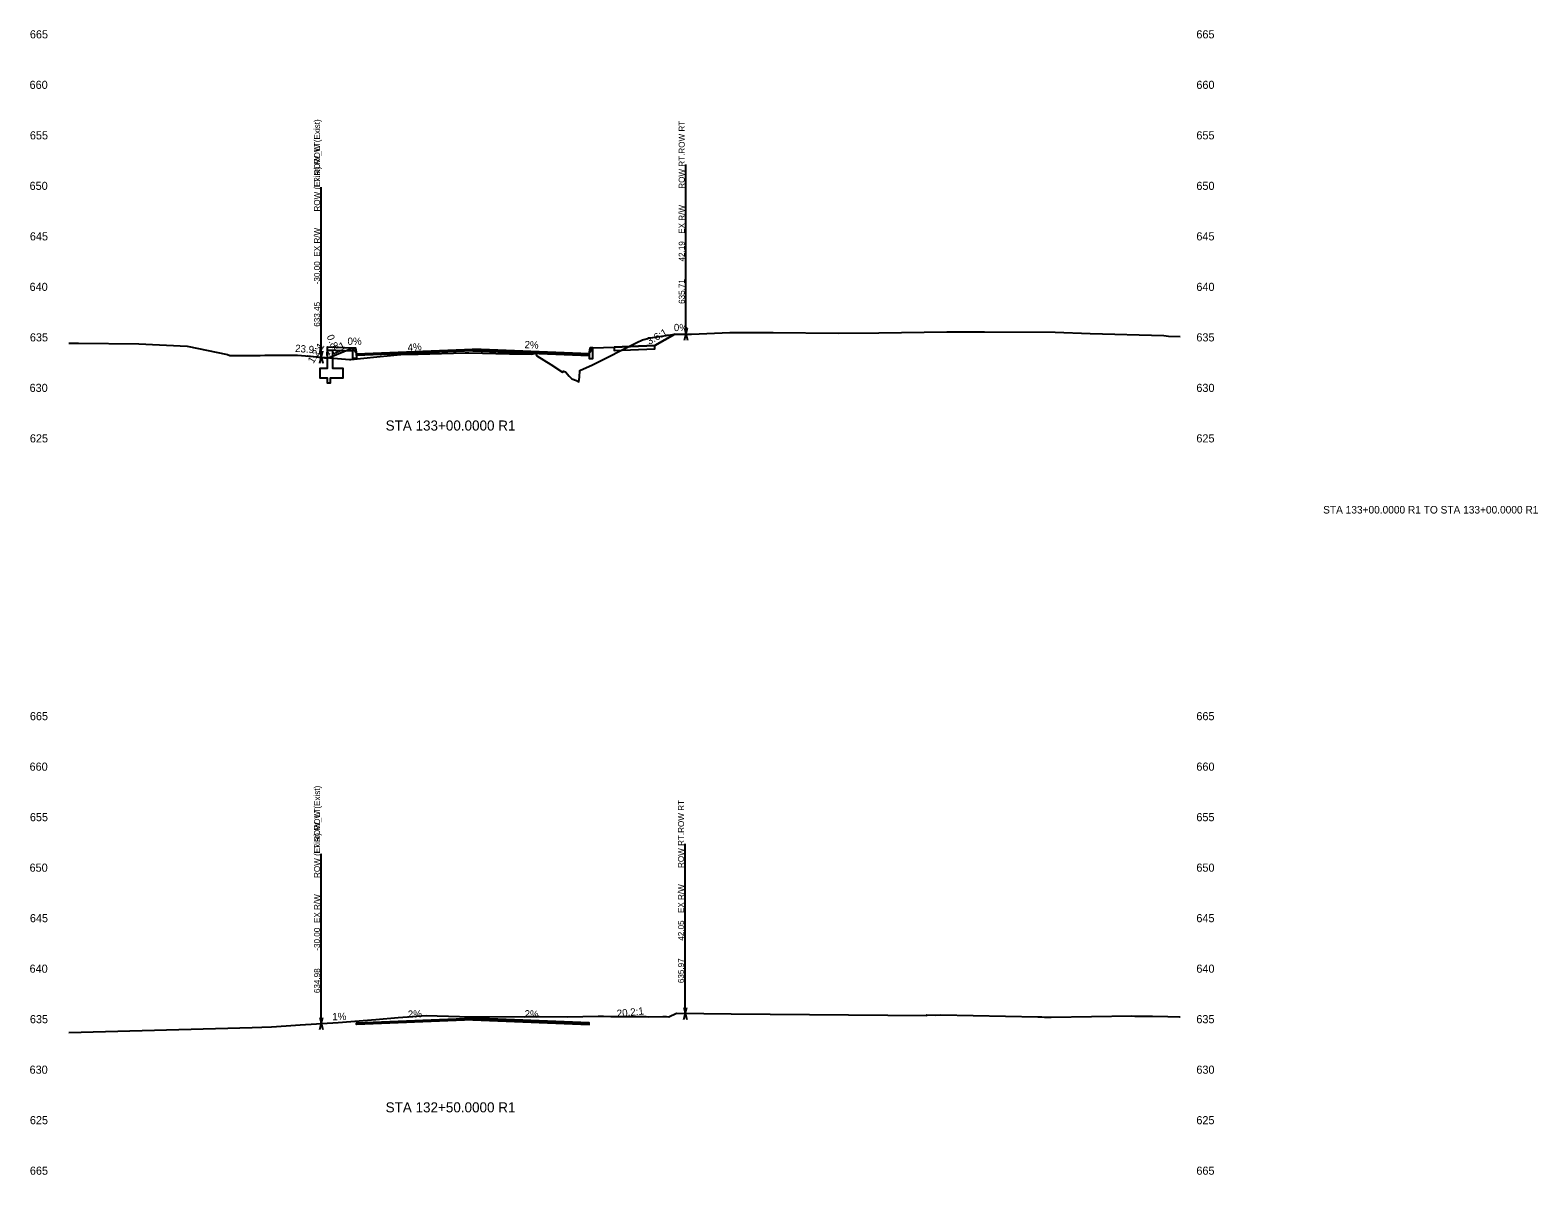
# Model space of a CAD drawing. Extents: x 2 to 741, y 16 to 2207.
# Drawn here: x 442.4 to 740.8, y 785 to 1011.6 of the extents above; entities that cross this region are included whole.
import ezdxf

# ---------------------------------------------------------------- set-up
doc = ezdxf.new("R2010")
doc.units = 0
for name, color, linetype in [('BORD_text_large_2', 7, 'Continuous'), ('Draft_XS_Feature_Name', 7, 'Continuous'), ('Draft_XS_Label', 7, 'Continuous'), ('Draft_XS_Point_Label_Indicator', 7, 'Continuous'), ('Draft_XS_Terminator', 7, 'Continuous'), ('Draft_XS_Text', 7, 'Continuous'), ('E_ROW', 7, 'Continuous'), ('E_Terrain_Exterior', 7, 'Continuous'), ('E_Terrain_Points_Low', 7, 'Continuous'), ('Grade_Veg_Grass', 7, 'Continuous'), ('P_XS_Sections', 7, 'Continuous'), ('Road_Curb', 7, 'Continuous'), ('Road_Pave_Asphalt', 7, 'Continuous'), ('Road_Sidewalk', 7, 'Continuous'), ('Struc_Wall', 7, 'Continuous'), ('Terrain_Design', 7, 'Continuous')]:
    doc.layers.add(name, color=color, linetype=linetype)

msp = doc.modelspace()

# ---------------------------------------------------------------- linework, layer by layer
at = {"layer": 'Draft_XS_Terminator'}
for p, q in [((572.19, 951.43), (572.19, 973.43)), ((500, 946.91), (500, 968.91)), ((500, 946.91), (500, 968.91)), ((572.05, 816.94), (572.05, 838.94)), ((500, 814.96), (500, 836.96)), ((500, 814.96), (500, 836.96))]:
    msp.add_line(p, q, dxfattribs=at)
at = {"layer": 'E_ROW'}
for p, q in [((572.19, 951.43), (572.19, 985.03)), ((500, 946.91), (500, 980.51)), ((500, 946.91), (500, 980.51)), ((571.89, 950.23), (572.49, 952.63)), ((571.89, 952.63), (572.49, 950.23)), ((499.7, 945.71), (500.3, 948.11)), ((499.7, 948.11), (500.3, 945.71)), ((499.7, 945.71), (500.3, 948.11)), ((499.7, 948.11), (500.3, 945.71)), ((500, 814.96), (500, 848.56)), ((500, 814.96), (500, 848.56)), ((572.05, 816.94), (572.05, 850.54)), ((571.75, 815.74), (572.35, 818.14)), ((571.75, 818.14), (572.35, 815.74)), ((499.7, 813.76), (500.3, 816.16)), ((499.7, 816.16), (500.3, 813.76)), ((499.7, 813.76), (500.3, 816.16)), ((499.7, 816.16), (500.3, 813.76))]:
    msp.add_line(p, q, dxfattribs=at)
at = {"layer": 'E_Terrain_Exterior'}
for points in [[(450, 949.63), (451.95, 949.63), (463.87, 949.53), (473.43, 949.05), (481.45, 947.44), (481.87, 947.2), (484.68, 947.22), (487.89, 947.24), (488.84, 947.25), (492.93, 947.28), (494.89, 947.3), (495.29, 947.3), (505.57, 946.44), (505.83, 946.43), (510.98, 946.92), (516.44, 947.45), (516.85, 947.46), (517.16, 947.5), (517.17, 947.5), (517.21, 947.5), (519, 947.49), (519.18, 947.5), (528.5, 947.71), (528.97, 947.76), (529.11, 947.75), (529.22, 947.75), (537.23, 947.57), (541.05, 947.53), (541.69, 947.48), (542.46, 947.66), (542.58, 947.22), (542.66, 947.15), (545.44, 945.45), (547.78, 943.91), (547.91, 943.97), (547.96, 944.08), (548.34, 943.98), (549.1, 943.11), (549.61, 942.6), (550.54, 942.27), (550.97, 941.97), (551.09, 942.9), (551.18, 944.21), (553.66, 945.39), (562.46, 949.76), (563.6, 950.33), (565.1, 950.68), (565.6, 950.76), (570, 951.44), (573.26, 951.42), (580.84, 951.74), (589.44, 951.77), (602.32, 951.65), (610.36, 951.67), (623.8, 951.88), (631.29, 951.87), (645.29, 951.8), (652.22, 951.54), (666.77, 951.16), (667.71, 951.05), (670, 950.97)], [(450, 813.15), (486.29, 814.17), (490.13, 814.29), (493.07, 814.49), (495.84, 814.69), (503.35, 815.17), (510.83, 815.77), (515.25, 816.11), (520.74, 816.5), (527.39, 816.3), (540.19, 816.28), (540.49, 816.31), (543.1, 816.32), (548.71, 816.27), (554.8, 816.39), (555.85, 816.38), (557.33, 816.35), (559.93, 816.33), (564.34, 816.3), (564.84, 816.29), (567.6, 816.32), (567.96, 816.32), (568.34, 816.3), (568.78, 816.28), (570.34, 816.96), (581.13, 816.85), (619.88, 816.51), (619.89, 816.63), (621.58, 816.6), (622.66, 816.63), (641.85, 816.28), (642.39, 816.26), (642.63, 816.25), (643.19, 816.23), (644.47, 816.18), (660.44, 816.44), (661.06, 816.43), (661.95, 816.42), (664.52, 816.38), (667.6, 816.32), (669.87, 816.28), (670, 816.28)]]:
    msp.add_lwpolyline(points, dxfattribs=at)
at = {"layer": 'Grade_Veg_Grass'}
for points in [[(570, 951.44), (566, 949.21), (566, 949.21)], [(497.25, 947.14), (501.25, 946.71), (501.25, 946.71)], [(553.75, 948.72), (558, 948.89)]]:
    msp.add_lwpolyline(points, dxfattribs=at)
at = {"layer": 'Road_Curb'}
for points in [[(507, 947.55), (507, 946.64), (506.25, 946.64), (506.25, 948.72), (506.77, 948.72), (507, 947.55)], [(553, 947.55), (553, 946.64), (553.75, 946.64), (553.75, 948.72), (553.23, 948.72), (553, 947.55)]]:
    msp.add_lwpolyline(points, dxfattribs=at)
at = {"layer": 'Road_Pave_Asphalt'}
for points in [[(530, 948.47), (530, 948.14), (507, 947.22), (507, 947.55), (530, 948.47)], [(530, 948.47), (530, 948.14), (553, 947.22), (553, 947.55), (530, 948.47)], [(530, 815.97), (530, 815.64), (507, 814.72), (507, 815.05), (530, 815.97)], [(530, 815.97), (530, 815.64), (553, 814.72), (553, 815.05), (530, 815.97)]]:
    msp.add_lwpolyline(points, dxfattribs=at)
at = {"layer": 'Road_Sidewalk'}
for points in [[(558, 948.89), (558, 948.22), (566, 948.54), (566, 949.21), (558, 948.89)], [(506.25, 948.72), (506.25, 948.05), (501.25, 948.25), (501.25, 948.92), (506.25, 948.72)]]:
    msp.add_lwpolyline(points, dxfattribs=at)
at = {"layer": 'Struc_Wall'}
msp.add_lwpolyline([(501.25, 944.71), (501.25, 946.71), (501.25, 946.71), (501.25, 948.25), (502.25, 948.21), (502.25, 948.21), (502.25, 944.71), (502.25, 944.71), (502.25, 944.71), (504.25, 944.71), (504.25, 942.71), (504.25, 942.71), (504.25, 942.71), (501.75, 942.71), (501.75, 941.71), (501.75, 941.71), (501.25, 941.71), (501.25, 941.71), (501.25, 941.71), (501.25, 942.71), (501.25, 942.71), (499.75, 942.71), (499.75, 942.71), (499.75, 944.71), (501.25, 944.71), (501.25, 944.71), (501.25, 944.71)], dxfattribs=at)
at = {"layer": 'Terrain_Design'}
for points in [[(497.25, 947.14), (497.25, 947.14), (501.25, 946.71), (506.25, 948.72), (506.77, 948.72), (507, 947.55), (530, 948.47), (530, 948.47), (553, 947.55), (553.23, 948.72), (553.75, 948.72), (558, 948.89), (566, 949.21), (570, 951.44)], [(501.25, 948.92), (501.25, 948.92), (506.25, 948.72), (506.77, 947.91), (507, 947.55), (530, 948.47), (530, 948.47), (553, 947.55), (553.23, 947.91), (553.75, 948.72), (558, 948.89), (566, 949.21), (570, 951.44)], [(507, 815.05), (530, 815.97), (553, 815.05)], [(507, 815.05), (530, 815.97), (553, 815.05)]]:
    msp.add_lwpolyline(points, dxfattribs=at)

# ---------------------------------------------------------------- texts
at = {"layer": 'BORD_text_large_2'}
msp.add_text('STA 133+00.0000 R1 TO STA 133+00.0000 R1', height=1.5, dxfattribs=at).set_placement((698.32, 915.92))
at = {"layer": 'Draft_XS_Feature_Name'}
for s, p in [('ROW (Exist).ROW (Exist)', (499.76, 975.71)), ('ROW RT.ROW RT', (571.95, 980.23)), ('ROW_LT.ROW_LT', (499.76, 975.71)), ('ROW (Exist).ROW (Exist)', (499.76, 843.76)), ('ROW_LT.ROW_LT', (499.76, 843.76)), ('ROW RT.ROW RT', (571.81, 845.74))]:
    msp.add_text(s, height=1.2, rotation=90, dxfattribs=at).set_placement(p)
at = {"layer": 'Draft_XS_Label'}
for s, p in [('42.19', (571.95, 965.83)), ('-30.00', (499.76, 961.31)), ('-30.00', (499.76, 961.31)), ('635.71', (571.95, 957.43)), ('633.45', (499.76, 952.91)), ('633.45', (499.76, 952.91)), ('-30.00', (499.76, 829.36)), ('-30.00', (499.76, 829.36)), ('42.05', (571.81, 831.34)), ('635.97', (571.81, 822.94)), ('634.98', (499.76, 820.96)), ('634.98', (499.76, 820.96))]:
    msp.add_text(s, height=1.2, rotation=90, dxfattribs=at).set_placement(p)
at = {"layer": 'Draft_XS_Point_Label_Indicator'}
for p in [(565.99, 949.2), (569.99, 951.43), (497.24, 947.12), (501.24, 948.91), (502.15, 946.7), (506.24, 948.71), (506.76, 948.71), (506.99, 947.54), (506.99, 946.62), (552.99, 947.54), (552.99, 946.62), (553.22, 948.71), (553.74, 948.71), (557.99, 948.88), (506.99, 815.04), (552.99, 815.04)]:
    msp.add_text('X', height=0.024, dxfattribs=at).set_placement(p)
at = {"layer": 'Draft_XS_Text'}
for s, height, p in [('665', 1.608, (442.32, 1010)), ('665', 1.608, (673.22, 1010)), ('660', 1.608, (442.26, 1000)), ('660', 1.608, (673.22, 1000)), ('655', 1.608, (442.32, 990)), ('655', 1.608, (673.22, 990)), ('650', 1.608, (442.26, 980)), ('650', 1.608, (673.22, 980)), ('645', 1.608, (442.32, 970)), ('645', 1.608, (673.22, 970)), ('640', 1.608, (442.26, 960)), ('640', 1.608, (673.22, 960)), ('635', 1.608, (442.32, 950)), ('635', 1.608, (673.22, 950)), ('630', 1.608, (442.26, 940)), ('630', 1.608, (673.22, 940)), ('STA 133+00.0000 R1', 1.992, (512.74, 932.35)), ('625', 1.608, (442.32, 930)), ('625', 1.608, (673.22, 930)), ('665', 1.608, (442.32, 875)), ('665', 1.608, (673.22, 875)), ('660', 1.608, (442.26, 865)), ('660', 1.608, (673.22, 865)), ('655', 1.608, (442.32, 855)), ('655', 1.608, (673.22, 855)), ('650', 1.608, (442.26, 845)), ('650', 1.608, (673.22, 845)), ('645', 1.608, (442.32, 835)), ('645', 1.608, (673.22, 835)), ('640', 1.608, (442.26, 825)), ('640', 1.608, (673.22, 825)), ('635', 1.608, (442.32, 815)), ('635', 1.608, (673.22, 815)), ('630', 1.608, (442.26, 805)), ('630', 1.608, (673.22, 805)), ('STA 132+50.0000 R1', 1.992, (512.74, 797.35)), ('625', 1.608, (442.32, 795)), ('625', 1.608, (673.22, 795)), ('665', 1.608, (442.32, 785)), ('665', 1.608, (673.22, 785))]:
    msp.add_text(s, height=height, dxfattribs=at).set_placement(p)
for s, rotation, p in [('3.6:1', 29.1707, (564.91, 949.29)), ('0%', 359.6221, (569.79, 952.04)), ('23.9:1', 355.2173, (494.78, 947.95)), ('1.2:1', 58.1718, (498.43, 945.51)), ('4.1:1', 26.1582, (501.07, 946.84)), ('0.8:1', 292.5528, (501.04, 951)), ('0%', 360, (505.2, 949.32)), ('4%', 4.5657, (517.14, 948.05)), ('2%', 357.7094, (540.21, 948.67)), ('20.2:1', 5.6571, (558.57, 816.21)), ('1%', 0.7951, (502.18, 815.59)), ('2%', 2.2906, (517.16, 816.06)), ('2%', 357.7094, (540.21, 816.17))]:
    msp.add_text(s, height=1.44, rotation=rotation, dxfattribs=at).set_placement(p)
at = {"layer": 'E_ROW'}
for p in [(571.95, 971.31), (499.76, 966.79), (499.76, 966.79), (571.81, 836.82), (499.76, 834.84), (499.76, 834.84)]:
    msp.add_text('EX R/W', height=1.2, rotation=90, dxfattribs=at).set_placement(p)
at = {"layer": 'E_Terrain_Points_Low'}
for p in [(529.99, 948.46), (529.99, 815.96)]:
    msp.add_text('X', height=0.024, dxfattribs=at).set_placement(p)
at = {"layer": 'P_XS_Sections'}
for p in [(450, 930), (450, 795)]:
    msp.add_text('-', height=0.0001, dxfattribs=at).set_placement(p)

doc.saveas('drawing.dxf')
